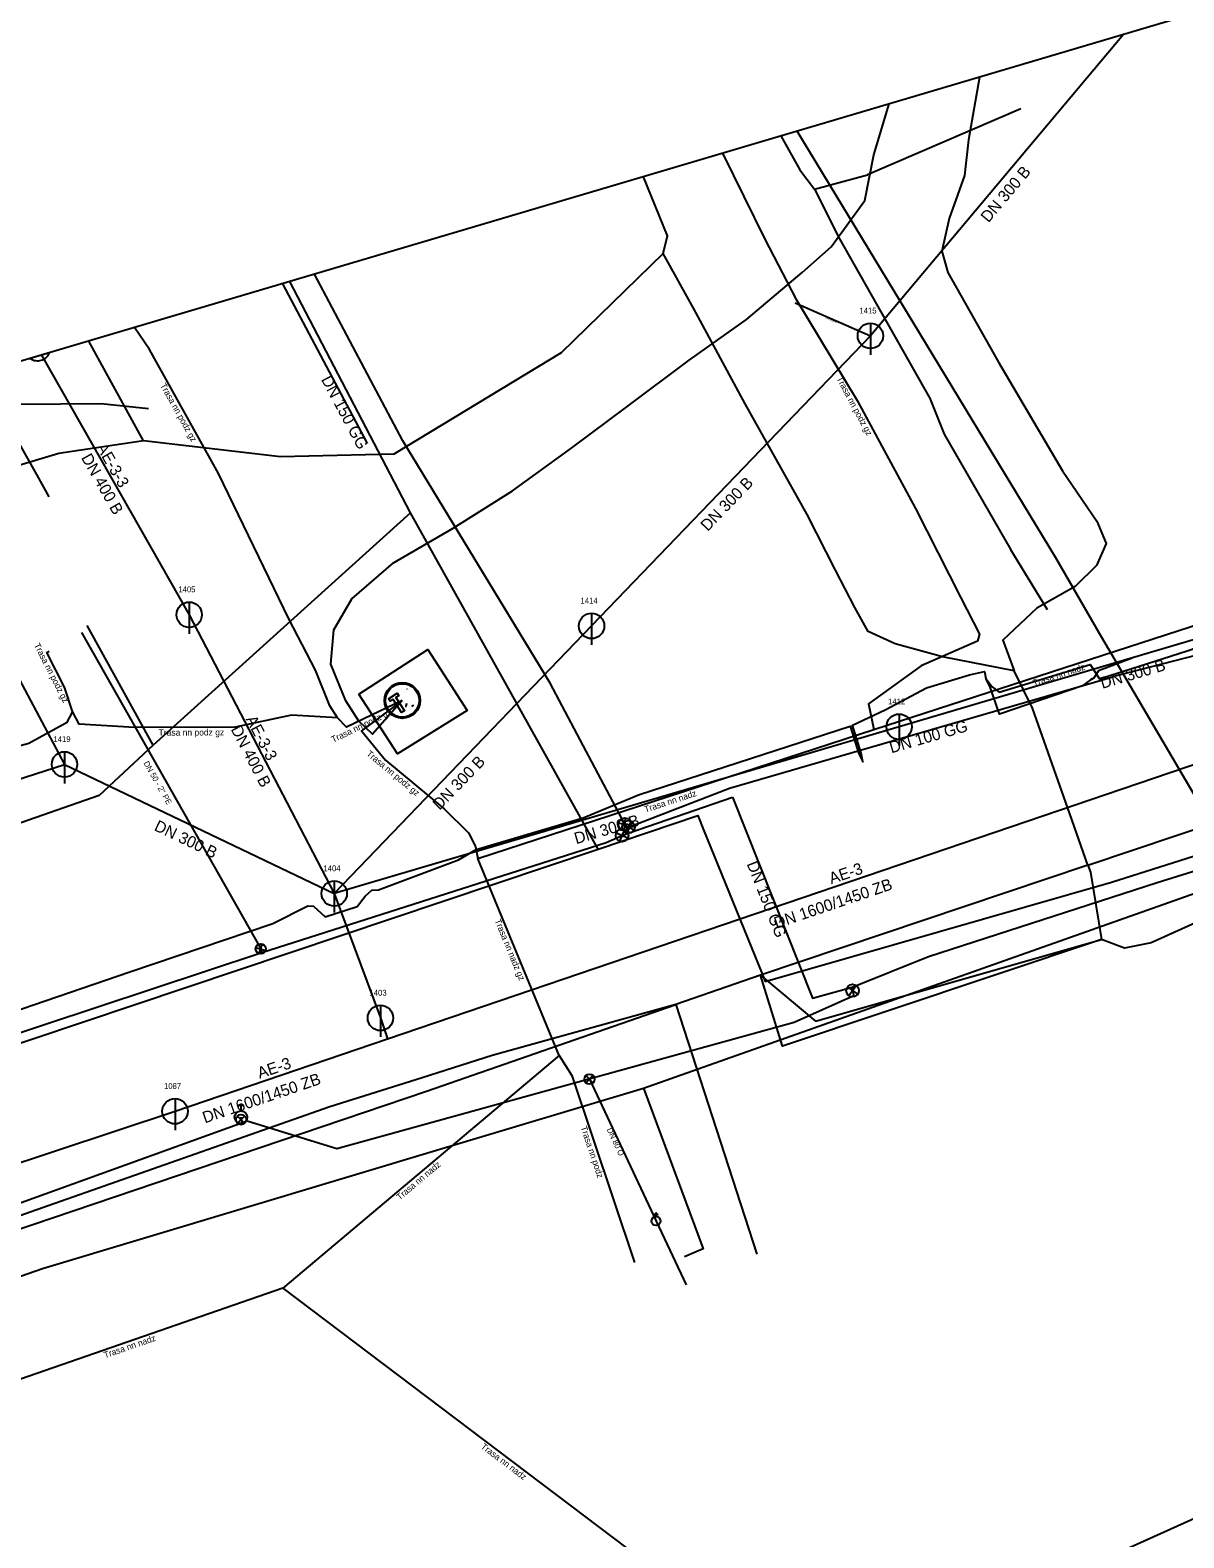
# Model space of a CAD drawing. Extents: x -493753 to -49291, y -1127285 to -112662.
# Drawn here: x -493239.7 to -493148.8, y -1126714.4 to -1126595.6 of the extents above; entities that cross this region are included whole.
import ezdxf

# ---------------------------------------------------------------- set-up
doc = ezdxf.new("R2010")
doc.units = 0
for name, color, linetype in [('Vrstva 1', 7, 'Continuous'), ('Vrstva 11', 7, 'Continuous'), ('Vrstva 15', 7, 'Continuous'), ('Vrstva 17', 7, 'Continuous'), ('Vrstva 19', 7, 'Continuous'), ('Vrstva 20', 7, 'Continuous'), ('Vrstva 22', 7, 'Continuous'), ('Vrstva 24', 7, 'Continuous'), ('Vrstva 25', 7, 'Continuous'), ('Vrstva 26', 7, 'Continuous'), ('Vrstva 39', 7, 'Continuous'), ('Vrstva 45', 7, 'Continuous'), ('Vrstva 5', 7, 'Continuous'), ('Vrstva 6', 7, 'Continuous'), ('Vrstva 8', 7, 'Continuous'), ('Vrstva 9', 7, 'Continuous')]:
    doc.layers.add(name, color=color, linetype=linetype)

# ---------------------------------------------------------------- blocks, each defined once
blk = doc.blocks.new('_UZAVE')
at = {"layer": 'Vrstva 1'}
for p, q in [((-0.035, -0.035), (0.035, 0.035)), ((0.035, -0.035), (-0.035, 0.035))]:
    blk.add_line(p, q, dxfattribs=at)
for radius in [0.05, 0.0025]:
    blk.add_circle((0, 0), radius, dxfattribs=at)
blk = doc.blocks.new('_UZAV0')
at = {"layer": 'Vrstva 1'}
for p, q in [((-0.035, -0.035), (0.035, 0.035)), ((0.035, -0.035), (-0.035, 0.035))]:
    blk.add_line(p, q, dxfattribs=at)
for radius in [0.05, 0.0025]:
    blk.add_circle((0, 0), radius, dxfattribs=at)
blk = doc.blocks.new('_HYDRA')
at = {"layer": 'Vrstva 1'}
for p, q in [((-0.0225, 0.095), (0.0225, 0.095)), ((0, 0.095), (0, 0.05))]:
    blk.add_line(p, q, dxfattribs=at)
blk.add_circle((0, 0), 0.05, dxfattribs=at)
blk = doc.blocks.new('_SACHT')
at = {"layer": 'Vrstva 1'}
blk.add_line((0, 0.035), (0, 0.05), dxfattribs=at)
blk.add_lwpolyline([(-0.015, 0.05), (0, 0.065), (0.015, 0.05), (0.0025, 0.05)], close=True, dxfattribs=at)
blk.add_circle((0, 0), 0.035, dxfattribs=at)
blk = doc.blocks.new('_SACH0')
at = {"layer": 'Vrstva 1'}
blk.add_line((0, 0.05), (0, -0.075), dxfattribs=at)
blk.add_circle((0, 0), 0.05, dxfattribs=at)

msp = doc.modelspace()

# ---------------------------------------------------------------- linework, layer by layer
at = {"layer": 'Vrstva 1'}
for p, q in [((-492950.39, -1126535.73), (-493753.13, -1126773.63)), ((-493230.04, -1126651.94), (-493235.22, -1126642.52))]:
    msp.add_line(p, q, dxfattribs=at)
for points in [[(-493386.97, -1126735.58), (-493385.48, -1126734.62), (-493337.07, -1126719.76), (-493332.99, -1126718.51), (-493329.52, -1126722.33), (-493310.17, -1126716.12), (-493297.1, -1126711.97), (-493263.47, -1126701.76), (-493238.75, -1126693.15), (-493207.17, -1126683.67), (-493191.4, -1126678.95), (-493125, -1126655.47), (-493062.97, -1126633.54), (-492997.53, -1126590.18)], [(-493194.98, -1126660.12), (-493209.76, -1126633.64), (-493219.26, -1126615.41)], [(-493209.76, -1126633.64), (-493230.04, -1126651.94), (-493234.28, -1126655.91), (-493248.76, -1126660.95), (-493268.92, -1126668.52), (-493287.81, -1126675.1), (-493306.69, -1126680.92), (-493310.18, -1126682.09), (-493322.36, -1126686.19), (-493334.27, -1126691.15), (-493353.31, -1126697.81), (-493367.19, -1126701.2), (-493385.36, -1126705.64), (-493390.85, -1126713.43)], [(-493385.61, -1126724.05), (-493194.98, -1126660.12), (-493187.12, -1126657.48), (-493186.67, -1126658.59), (-493182.04, -1126669.95), (-493181.8, -1126670.54), (-493154.52, -1126662.73), (-493143.18, -1126659.14), (-493127.68, -1126653.85), (-493118.08, -1126650.58), (-493099.29, -1126643.04), (-493095.87, -1126641.67), (-493086.94, -1126637.67)], [(-493191.4, -1126678.95), (-493186.7, -1126691.6), (-493188.17, -1126692.24)]]:
    msp.add_lwpolyline(points, dxfattribs=at)
at = {"layer": 'Vrstva 11'}
for points in [[(-493155.32, -1126667.23), (-493180.46, -1126675.64), (-493182.18, -1126670.05)], [(-493188.86, -1126672.37), (-493203.32, -1126676.39), (-493208.85, -1126678.14), (-493216.1, -1126680.42), (-493240.17, -1126688.88), (-493264.71, -1126697.85), (-493290.31, -1126705.77), (-493311.07, -1126713.16), (-493336.35, -1126722.15), (-493384.4, -1126738.16)]]:
    msp.add_lwpolyline(points, dxfattribs=at)
at = {"layer": 'Vrstva 15'}
for p, q in [((-493153.58, -1126595.95), (-493173.52, -1126619.69)), ((-493179.46, -1126617.1), (-493173.52, -1126619.69)), ((-493173.52, -1126619.69), (-493195.49, -1126642.54)), ((-493238.82, -1126621.21), (-493227.19, -1126641.66)), ((-493132.85, -1126639.14), (-493171.26, -1126650.48)), ((-493227.19, -1126641.66), (-493215.76, -1126663.62)), ((-493195.49, -1126642.54), (-493215.76, -1126663.62)), ((-493241.04, -1126645.9), (-493237.02, -1126653.45)), ((-493171.26, -1126650.48), (-493215.76, -1126663.62)), ((-493211.56, -1126675.07), (-493138.24, -1126650.12)), ((-493257.17, -1126659.99), (-493237.02, -1126653.45)), ((-493237.02, -1126653.45), (-493215.76, -1126663.62)), ((-493215.76, -1126663.62), (-493212.13, -1126673.42)), ((-493212.13, -1126673.42), (-493211.56, -1126675.07)), ((-493228.31, -1126680.77), (-493211.56, -1126675.07)), ((-493286.69, -1126700.12), (-493228.31, -1126680.77))]:
    msp.add_line(p, q, dxfattribs=at)
at = {"layer": 'Vrstva 17'}
msp.add_line((-493238.2, -1126621.03), (-493239.71, -1126621.47), dxfattribs=at)
msp.add_arc((-493239.13, -1126620.66), 1, 234.553, 338.4631, dxfattribs=at)
at = {"layer": 'Vrstva 20'}
for p, q in [((-493192.54, -1126658.85), (-493184.38, -1126656.04)), ((-493192.7, -1126658.44), (-493192.88, -1126658.16)), ((-493192.7, -1126658.44), (-493192.59, -1126658.38)), ((-493174.97, -1126671), (-493174.93, -1126671.26)), ((-493195.66, -1126678.24), (-493190.41, -1126689.42)), ((-493190.41, -1126689.42), (-493188.05, -1126694.45))]:
    msp.add_line(p, q, dxfattribs=at)
for points in [[(-493174.97, -1126671), (-493168.95, -1126668.59), (-493150.92, -1126662.76), (-493136.6, -1126658.3), (-493104.67, -1126647.66), (-493085.83, -1126640.49), (-493075.06, -1126636.63), (-493066.87, -1126632.41), (-493057.12, -1126625.67), (-493040.16, -1126614.7), (-493027.86, -1126606.78), (-493012.63, -1126597.22), (-493006.68, -1126593.57), (-492997.84, -1126587.96), (-492995.32, -1126586.25), (-492988.81, -1126582.57), (-492979.95, -1126576.81), (-492978.81, -1126576)], [(-493104.48, -1126692.95), (-493105.85, -1126691.77), (-493142.64, -1126662.49), (-493145.44, -1126660.21), (-493155.3, -1126643.44), (-493158.9, -1126637.17), (-493179.3, -1126603.57)], [(-493192.88, -1126658.16), (-493198.74, -1126647.06), (-493210.35, -1126627.97), (-493217.32, -1126614.84)], [(-493085.26, -1126622.7), (-493089.17, -1126624.53), (-493103.36, -1126630.39), (-493118.4, -1126636.33), (-493141.27, -1126643.17), (-493154.23, -1126646.51)], [(-493235.68, -1126643.05), (-493221.56, -1126667.98), (-493221.47, -1126668.27)], [(-493192.59, -1126658.38), (-493184.61, -1126655.33), (-493154.23, -1126646.51)], [(-493184.38, -1126656.04), (-493178.09, -1126671.85), (-493174.97, -1126671)], [(-493388.95, -1126714.68), (-493385.51, -1126723.11), (-493350, -1126711.24), (-493334.27, -1126706.11), (-493304.84, -1126694.92), (-493282.08, -1126687.32), (-493265.19, -1126681.68), (-493242.97, -1126675.39), (-493221.47, -1126668.27), (-493194.34, -1126659.59), (-493193.09, -1126659.04)], [(-493193.09, -1126659.04), (-493192.54, -1126658.85), (-493192.7, -1126658.44)], [(-493174.93, -1126671.26), (-493174.82, -1126671.68), (-493179.54, -1126673.79), (-493215.57, -1126683.72), (-493222.63, -1126681.54), (-493265.09, -1126696.88), (-493320.52, -1126714.46), (-493431.04, -1126751.7), (-493465.39, -1126763.9), (-493480.64, -1126768.71), (-493511.98, -1126779.09), (-493513.24, -1126779.47)], [(-493223.12, -1126681.24), (-493223.11, -1126681.43), (-493223.03, -1126681.68)]]:
    msp.add_lwpolyline(points, dxfattribs=at)
at = {"layer": 'Vrstva 25'}
for points in [[(-493164.43, -1126646.67), (-493163.94, -1126647.33), (-493163.37, -1126647.77), (-493156.2, -1126645.58), (-493155.46, -1126646.71), (-493148.57, -1126644.5), (-493134.79, -1126639.78), (-493134.82, -1126639.02), (-493134.2, -1126638.71), (-493126.11, -1126636.12), (-493118.54, -1126633.31), (-493114.04, -1126631.81), (-493099.4, -1126625.88), (-493098.84, -1126625.76), (-493098.28, -1126625.42), (-493094.57, -1126623.87), (-493093.74, -1126623.83), (-493093.12, -1126623.22)], [(-493246.07, -1126674.64), (-493231.88, -1126669.78), (-493220.6, -1126665.97), (-493217.85, -1126664.6), (-493217.4, -1126664.62), (-493216.47, -1126665.46), (-493213.97, -1126664.63), (-493213.32, -1126663.84), (-493212.81, -1126663.36), (-493212.28, -1126663.32), (-493205.98, -1126660.97), (-493204.58, -1126660.16), (-493196.14, -1126657.65), (-493191.78, -1126655.85), (-493175.12, -1126650.44), (-493174.43, -1126652.62), (-493174.13, -1126653.25), (-493174.24, -1126652.56), (-493174.93, -1126650.36), (-493172.36, -1126649.14), (-493169.1, -1126647.41), (-493165.71, -1126646.39), (-493164.54, -1126646.12), (-493164.43, -1126646.67)], [(-493152.91, -1126645.09), (-493155.56, -1126646.08), (-493155.94, -1126646.69), (-493156.04, -1126646.71), (-493156.18, -1126646.78), (-493156.82, -1126647.26), (-493163.36, -1126649.49), (-493164.11, -1126647.29), (-493164.43, -1126646.67)]]:
    msp.add_lwpolyline(points, dxfattribs=at)
at = {"layer": 'Vrstva 26'}
for p, q in [((-493161.66, -1126601.8), (-493173.74, -1126607.02)), ((-493180.57, -1126603.95), (-493179.08, -1126606.62)), ((-493179.08, -1126606.62), (-493177.93, -1126608.14)), ((-493177.93, -1126608.14), (-493173.74, -1126607.02)), ((-493177.92, -1126608.14), (-493175.96, -1126612.05)), ((-493175.96, -1126612.05), (-493168.9, -1126624.51)), ((-493219.84, -1126615.59), (-493213.18, -1126628.18)), ((-493168.9, -1126624.51), (-493168.87, -1126624.55)), ((-493168.87, -1126624.55), (-493167.71, -1126627.43)), ((-493234.13, -1126625.04), (-493240.51, -1126625.09)), ((-493230.41, -1126625.45), (-493234.13, -1126625.04)), ((-493167.71, -1126627.43), (-493162.47, -1126636.54)), ((-493159.58, -1126641.27), (-493162.47, -1126636.54)), ((-493156.04, -1126646.71), (-493155.99, -1126646.75))]:
    msp.add_line(p, q, dxfattribs=at)
at = {"layer": 'Vrstva 39'}
for points in [[(-493164.93, -1126599.31), (-493165.79, -1126604.26), (-493166.12, -1126607.05), (-493167.32, -1126610.45), (-493167.9, -1126613.01), (-493167.42, -1126614.71), (-493163.42, -1126621.77), (-493158.38, -1126630.32), (-493155.68, -1126634.28), (-493154.94, -1126636.06), (-493155.7, -1126637.77), (-493157.38, -1126639.43), (-493160.4, -1126641.15), (-493163.1, -1126643.65), (-493162.2, -1126646.08)], [(-493189.86, -1126613.21), (-493189.51, -1126611.82), (-493191.4, -1126607.16)], [(-493189.86, -1126613.21), (-493197.89, -1126621.02), (-493211.07, -1126629.01), (-493220.01, -1126629.22), (-493230.78, -1126627.97)], [(-493162.2, -1126646.08), (-493167.85, -1126644.98), (-493171.56, -1126643.94), (-493173.7, -1126642.99), (-493174.74, -1126641.1), (-493176.27, -1126638.14), (-493178.51, -1126633.77), (-493183.39, -1126625.04), (-493187.46, -1126617.52), (-493189.86, -1126613.21)], [(-493230.78, -1126627.97), (-493235.11, -1126620.11)], [(-493230.78, -1126627.97), (-493237.47, -1126628.96), (-493243.79, -1126630.84)], [(-493156.38, -1126661.38), (-493124.88, -1126650.8), (-493109.06, -1126645.32), (-493090.65, -1126637.63), (-493079.53, -1126633.19)], [(-493081.08, -1126639.68), (-493098.01, -1126646.24), (-493113.1, -1126652.55), (-493129.78, -1126658.33), (-493142.88, -1126663.67), (-493151.41, -1126667.51), (-493153.5, -1126667.92), (-493155.32, -1126667.23)], [(-493156.38, -1126661.38), (-493157.8, -1126657.35), (-493160.75, -1126649.02), (-493162.2, -1126646.08)], [(-493156.38, -1126661.38), (-493182.18, -1126670.05)], [(-493156.38, -1126661.38), (-493156.19, -1126661.94), (-493155.32, -1126667.23)], [(-493182.18, -1126670.05), (-493177.84, -1126673.67), (-493155.32, -1126667.23)], [(-493182.18, -1126670.05), (-493188.86, -1126672.37)], [(-493391.48, -1126754), (-493384.29, -1126738.55), (-493336.24, -1126722.43), (-493208.49, -1126679.18), (-493188.86, -1126672.37)], [(-493188.86, -1126672.37), (-493182.46, -1126692.03)]]:
    msp.add_lwpolyline(points, dxfattribs=at)
at = {"layer": 'Vrstva 45'}
for p, q in [((-493243.46, -1126623.1), (-493239.23, -1126630.61)), ((-493239.23, -1126630.61), (-493238.25, -1126632.36))]:
    msp.add_line(p, q, dxfattribs=at)
at = {"layer": 'Vrstva 5'}
for points in [[(-493185.17, -1126605.31), (-493185.16, -1126605.36), (-493181.83, -1126612.08), (-493179.39, -1126616.77), (-493174.56, -1126624.78), (-493169.98, -1126633.3), (-493166.43, -1126640.27), (-493164.92, -1126643.19), (-493165.09, -1126643.73), (-493169.51, -1126645.68), (-493173.66, -1126648.67), (-493173.25, -1126650.69)], [(-493215.52, -1126649.78), (-493216.1, -1126648.84), (-493217.23, -1126646.03), (-493219.34, -1126641.97), (-493224.88, -1126630.54), (-493230.33, -1126620.76), (-493231.49, -1126619.04)], [(-493173.25, -1126650.69), (-493143.22, -1126640.97)], [(-493236.39, -1126649.27), (-493237.03, -1126647.36), (-493238.42, -1126644.63), (-493238.22, -1126644.53)], [(-493210.4, -1126648.41), (-493213.44, -1126649.87), (-493214.81, -1126650.51), (-493215.52, -1126649.78)], [(-493210.4, -1126648.41), (-493212.79, -1126650.2), (-493213.62, -1126650.81), (-493211.73, -1126653.12), (-493207.1, -1126656.95), (-493205.19, -1126658.85), (-493204.64, -1126659.92), (-493204.44, -1126660.87)], [(-493236.39, -1126649.27), (-493236.86, -1126650.17), (-493239.83, -1126651.79), (-493245.76, -1126653.42), (-493256.14, -1126655.64), (-493256.92, -1126655.1)], [(-493215.52, -1126649.78), (-493219.13, -1126649.56), (-493223.58, -1126650.51), (-493231.49, -1126650.55), (-493235.85, -1126650.27), (-493236.39, -1126649.27)], [(-493204.44, -1126660.87), (-493173.25, -1126650.69)], [(-493198.04, -1126676.37), (-493204.44, -1126660.87)], [(-493198.04, -1126676.37), (-493219.81, -1126694.7)], [(-493198.04, -1126676.37), (-493197.04, -1126677.96), (-493192.1, -1126692.69)], [(-493219.81, -1126694.7), (-493243.09, -1126702.76)], [(-493219.81, -1126694.7), (-493183.57, -1126722.08)]]:
    msp.add_lwpolyline(points, dxfattribs=at)
at = {"layer": 'Vrstva 6'}
for points in [[(-493210.4, -1126648.41), (-493212.74, -1126651.08), (-493213.83, -1126650.05), (-493214.86, -1126648.45), (-493216.03, -1126645.54), (-493215.8, -1126642.84), (-493214.39, -1126640.41), (-493211.09, -1126637.56), (-493206.4, -1126634.83), (-493201.73, -1126631.91), (-493197.05, -1126628.52), (-493192.72, -1126625.28), (-493187.81, -1126621.62), (-493183.28, -1126618.41), (-493178.91, -1126614.71), (-493176.6, -1126612.69), (-493173.95, -1126609.03), (-493173.26, -1126605.43), (-493172.03, -1126601.42)], [(-493089.02, -1126668.7), (-493097.55, -1126670.77), (-493102.89, -1126674.28), (-493107.46, -1126678.08), (-493109.76, -1126680.24), (-493114.75, -1126688.53), (-493118.01, -1126692.46), (-493120.49, -1126694.75), (-493124.18, -1126696.61), (-493129.09, -1126697.4), (-493133.38, -1126697.66), (-493134.27, -1126698.24), (-493137.89, -1126703.73), (-493144.02, -1126711.06), (-493158.37, -1126717.52), (-493159.88, -1126717.4)]]:
    msp.add_lwpolyline(points, dxfattribs=at)
at = {"layer": 'Vrstva 8'}
for points in [[(-493213.82, -1126647.91), (-493208.38, -1126644.41), (-493205.3, -1126649.19), (-493210.79, -1126652.62)], [(-493211.49, -1126648.28), (-493210.81, -1126647.84), (-493210.68, -1126648.05), (-493210.91, -1126648.19), (-493210.24, -1126649.23), (-493210.47, -1126649.37), (-493211.13, -1126648.33), (-493211.36, -1126648.48)]]:
    msp.add_lwpolyline(points, close=True, dxfattribs=at)
for points in [[(-493210.25, -1126647.74), (-493210.25, -1126647.74)], [(-493210.01, -1126647.51), (-493210.02, -1126647.5)], [(-493210.08, -1126648.65), (-493210.12, -1126648.88), (-493210.11, -1126648.89)], [(-493209.73, -1126648.66), (-493209.74, -1126648.66)], [(-493209.66, -1126648.9), (-493209.54, -1126648.82), (-493209.49, -1126648.76)]]:
    msp.add_lwpolyline(points, dxfattribs=at)
for radius in [1.41, 1.32]:
    msp.add_circle((-493210.4, -1126648.41), radius, dxfattribs=at)

# ---------------------------------------------------------------- block references
at = {"layer": 'Vrstva 17', "xscale": 19.997500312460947, "yscale": 19.997500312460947}
for p in [(-493173.52, -1126619.69), (-493227.19, -1126641.66), (-493195.49, -1126642.54), (-493171.26, -1126650.48), (-493237.02, -1126653.45), (-493215.76, -1126663.62), (-493212.13, -1126673.42), (-493228.31, -1126680.77)]:
    msp.add_blockref('_SACH0', p, dxfattribs=at)
at = {"layer": 'Vrstva 22'}
for name, p, xscale, yscale, rotation in [('_UZAVE', (-493192.88, -1126658.16), 9.998750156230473, 9.998750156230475, 129.861385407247), ('_UZAVE', (-493192.59, -1126658.38), 9.998750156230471, 9.99875015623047, 16.496591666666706), ('_UZAVE', (-493193.09, -1126659.04), 9.998750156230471, 9.99875015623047, -158.27129501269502), ('_UZAV0', (-493221.56, -1126667.98), 7.999000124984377, 7.999000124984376, -62.008966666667), ('_UZAVE', (-493174.93, -1126671.26), 9.998750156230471, 9.99875015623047, -80.84229749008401)]:
    msp.add_blockref(name, p, dxfattribs=dict(at, xscale=xscale, yscale=yscale, rotation=rotation))
for name, p, xscale, yscale in [('_UZAV0', (-493195.66, -1126678.24), 7.999000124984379, 7.999000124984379), ('_HYDRA', (-493223.12, -1126681.24), 9.998750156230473, 9.998750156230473), ('_UZAV0', (-493223.11, -1126681.43), 7.999000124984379, 7.999000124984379), ('_SACHT', (-493190.41, -1126689.42), 9.998750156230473, 9.998750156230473)]:
    msp.add_blockref(name, p, dxfattribs=dict(at, xscale=xscale, yscale=yscale))

# ---------------------------------------------------------------- texts
at = {"layer": 'Vrstva 19'}
for s, height, rotation, p in [('DN 300 B', 0.91, 49.9768, (-493164.22, -1126610.83)), ('DN 200 B', 0.16, 336.4446, (-493177.07, -1126618.32)), ('AE-3-3', 0.91, 299.626, (-493234.54, -1126628.45)), ('DN 400 B', 0.91, 299.626, (-493235.73, -1126629.29)), ('DN 300 B', 0.91, 46.1222, (-493186.34, -1126635.14)), ('DN 300 B', 0.91, 16.4528, (-493155.25, -1126647.5)), ('DN 400 B', 0.91, 297.4986, (-493223.94, -1126650.67)), ('AE-3-3', 0.91, 297.4986, (-493222.76, -1126649.88)), ('DN 300 B', 0.91, 46.1224, (-493207.46, -1126657.1)), ('DN 300 B', 0.91, 334.4351, (-493230.02, -1126658.61)), ('DN 300 B', 0.91, 16.45, (-493196.7, -1126659.74)), ('AE-3', 0.91, 18.7936, (-493176.6, -1126662.89)), ('DN 1600/1450 ZB', 0.9099, 18.7936, (-493180.93, -1126666.4)), ('AE-3', 0.91, 18.7934, (-493221.64, -1126678.22)), ('DN 1600/1450 ZB', 0.9099, 18.7934, (-493225.96, -1126681.73))]:
    msp.add_text(s, height=height, rotation=rotation, dxfattribs=at).set_placement(p)
for s, p in [('1415', (-493174.39, -1126617.93)), ('1405', (-493228.05, -1126639.89)), ('1414', (-493196.36, -1126640.78)), ('1412', (-493172.13, -1126648.72)), ('1419', (-493237.89, -1126651.68)), ('1404', (-493216.62, -1126661.86)), ('1403', (-493212.99, -1126671.66)), ('1087', (-493229.18, -1126679.01))]:
    msp.add_text(s, height=0.455, dxfattribs=at).set_placement(p)
at = {"layer": 'Vrstva 24'}
for s, height, rotation, p in [('DN 150 GG', 0.91, 297.9735, (-493216.82, -1126623.12)), ('DN 100 GG', 0.91, 16.2049, (-493171.87, -1126652.58)), ("DN 50 - 2'' PE", 0.455, 299.514, (-493230.81, -1126653.35)), ('DN 150 GG', 0.91, 291.6958, (-493183.28, -1126661.28)), ('DN 80 O', 0.455, 295.1293, (-493194.31, -1126682.2))]:
    msp.add_text(s, height=height, rotation=rotation, dxfattribs=at).set_placement(p)
at = {"layer": 'Vrstva 9'}
for s, rotation, p in [('Trasa nn podz gz', 299.1292, (-493229.5, -1126623.59)), ('Trasa nn podz gz', 298.2606, (-493176.22, -1126623.06)), ('Trasa nn podz gz', 296.9833, (-493239.44, -1126644.05)), ('Trasa nn nadz', 17.9357, (-493160.63, -1126647.29)), ('Trasa nn podz gz', 25.7421, (-493215.85, -1126651.75)), ('Trasa nn podz gz', 0.2897, (-493229.6, -1126651.19)), ('Trasa nn podz gz', 320.402, (-493213.27, -1126652.69)), ('Trasa nn nadz', 18.0759, (-493191.24, -1126657.25)), ('Trasa nn nadz gz', 292.4242, (-493203.14, -1126665.75)), ('Trasa nn podz', 288.5376, (-493196.36, -1126682.03)), ('Trasa nn nadz', 40.095, (-493210.6, -1126687.8)), ('Trasa nn nadz', 19.0954, (-493233.82, -1126700.23)), ('Trasa nn nadz', 322.9314, (-493204.26, -1126707.27))]:
    msp.add_text(s, height=0.5, rotation=rotation, dxfattribs=at).set_placement(p)

doc.saveas('drawing.dxf')
